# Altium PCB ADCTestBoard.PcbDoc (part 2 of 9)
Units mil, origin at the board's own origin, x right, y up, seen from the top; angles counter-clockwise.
Board outline 11022.62 x 9187 mil, 8 copper layers (TopLayer, InternalPlane1, InternalPlane2, InternalPlane3, InternalPlane4, InternalPlane5, MidLayer1, BottomLayer), stack 103.8 mil thick; 1282 components, 637 nets, 4473 pads, 1306 vias.
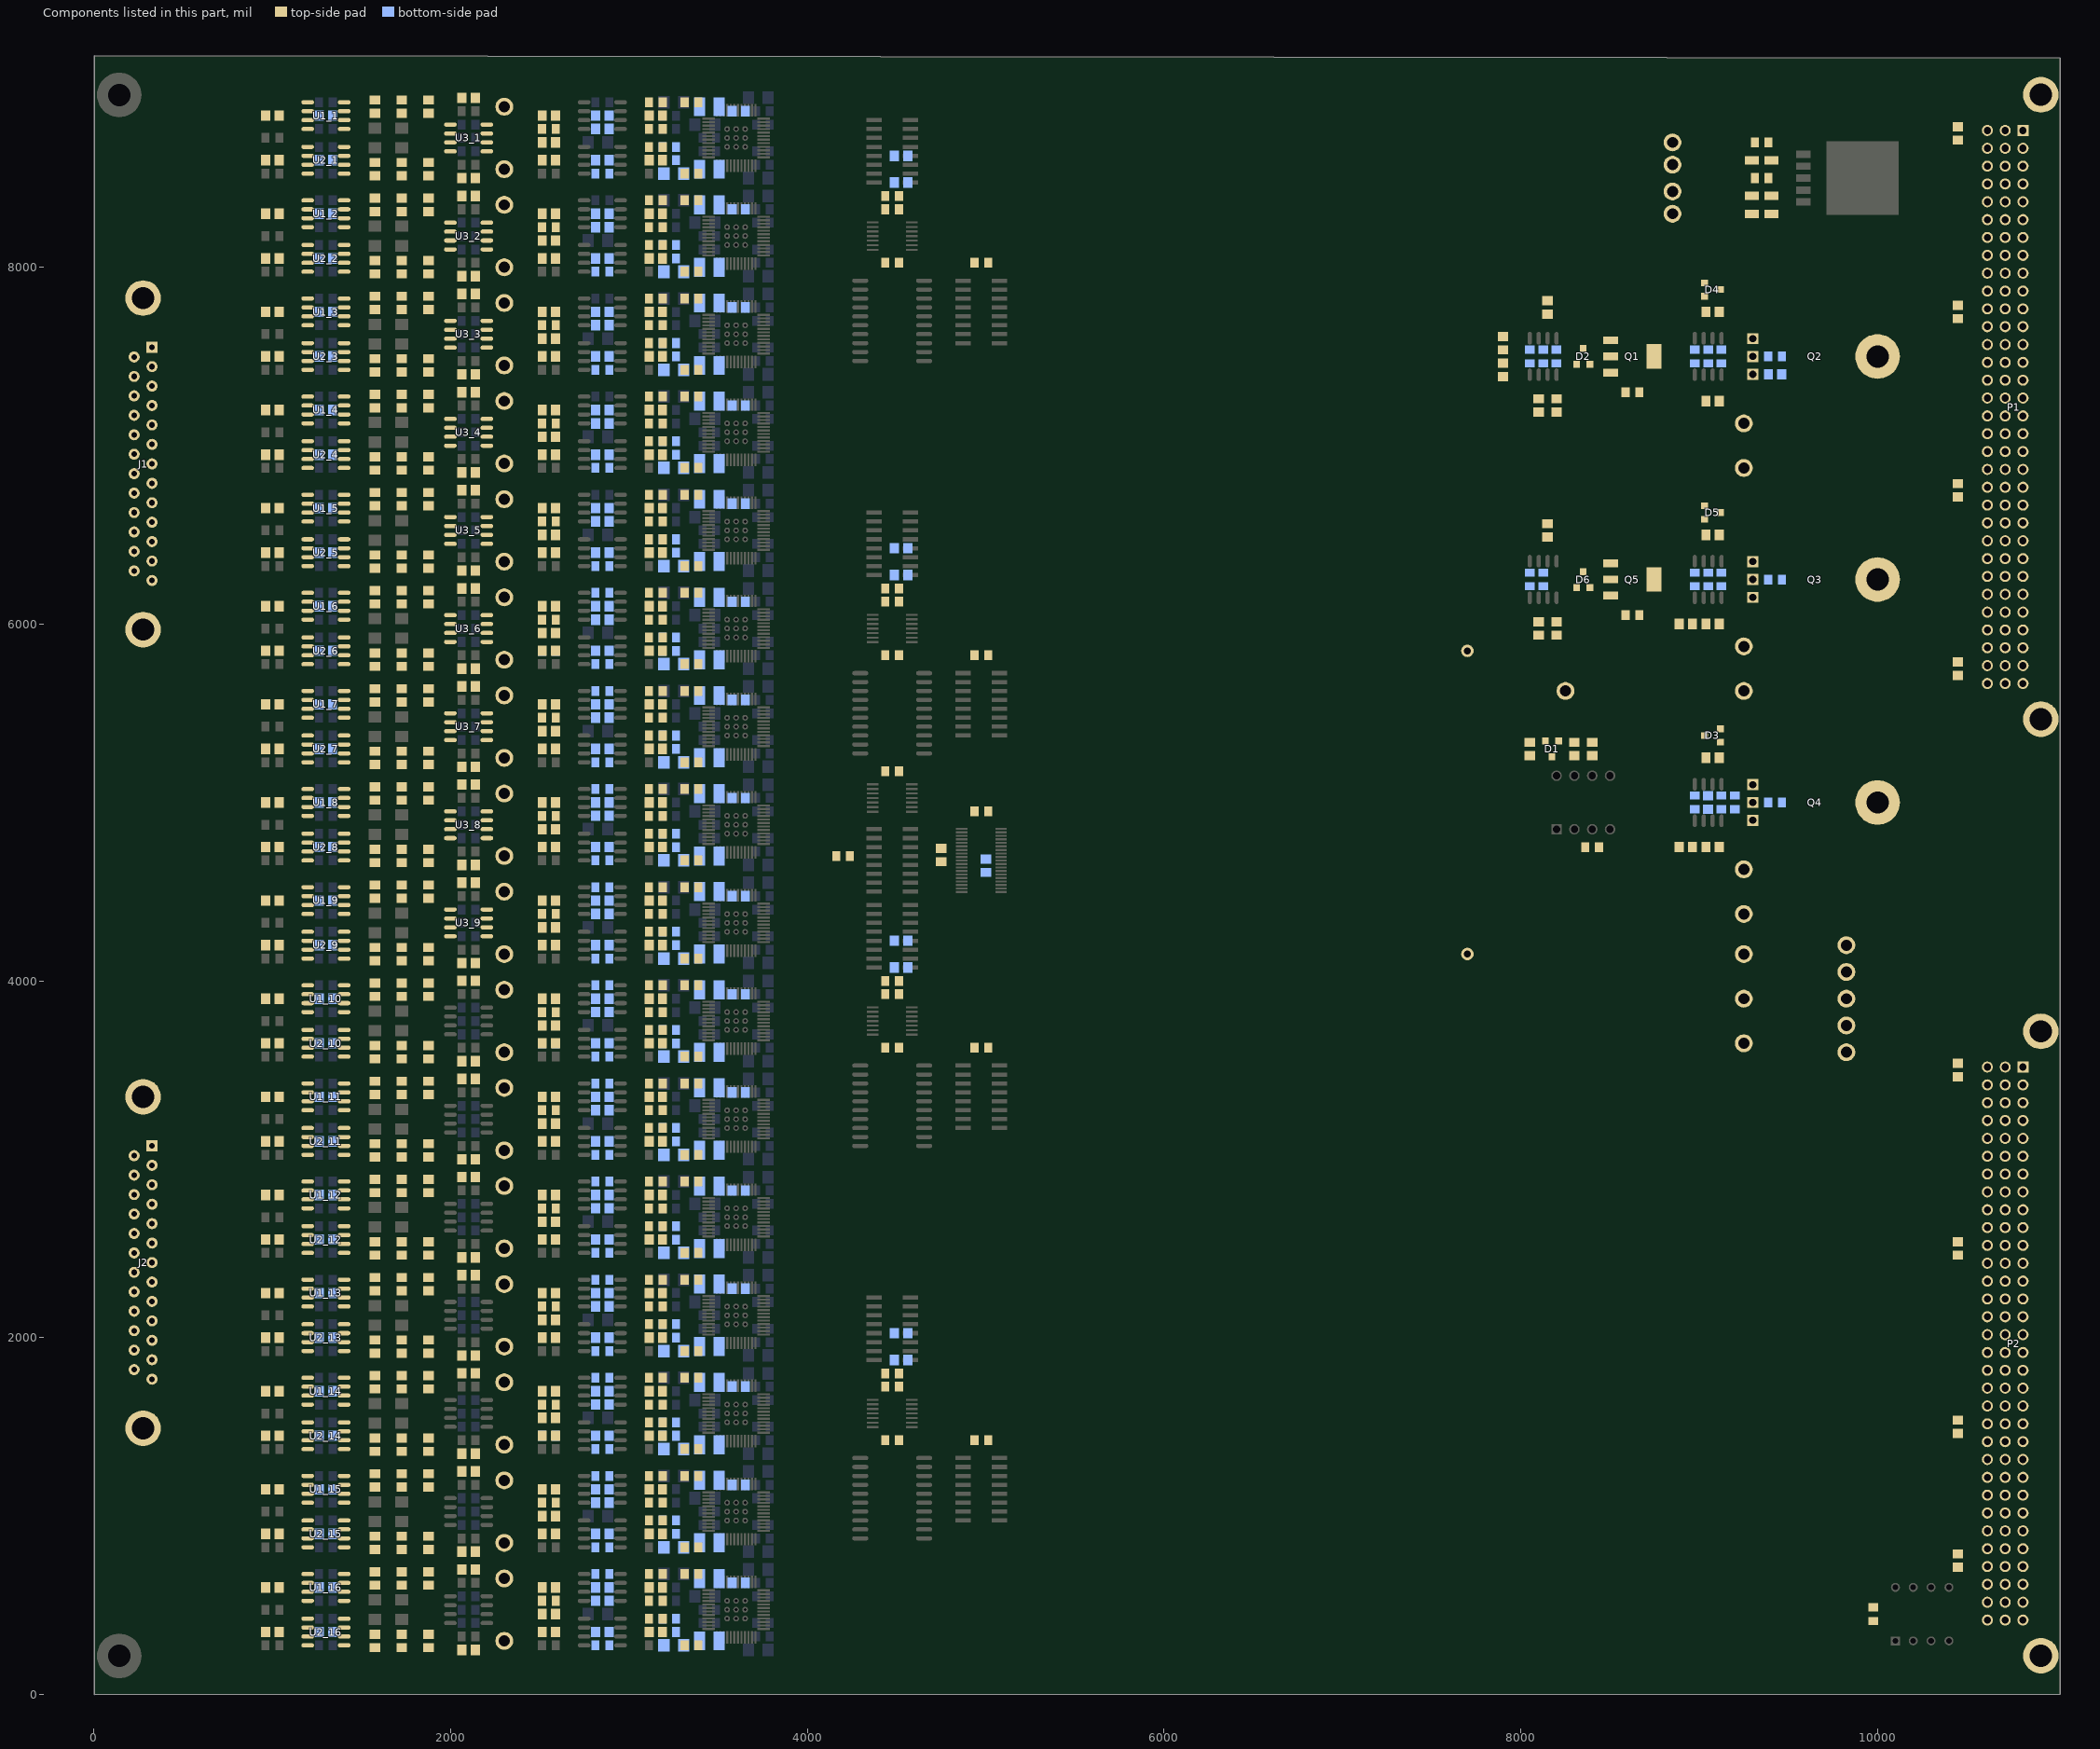
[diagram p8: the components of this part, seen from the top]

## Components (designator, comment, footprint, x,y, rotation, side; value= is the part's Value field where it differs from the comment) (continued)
C29_6 "1u" CC2013-0805 2850,6175 r180 bottom (schematic designator C29)
C29_7 "1u" CC2013-0805 2850,5625 r180 bottom (schematic designator C29)
C29_8 "1u" CC2013-0805 2850,5075 r180 bottom (schematic designator C29)
C29_9 "1u" CC2013-0805 2850,4525 r180 bottom (schematic designator C29)
C29_10 "1u" CC2013-0805 2850,3975 r180 bottom (schematic designator C29)
C29_11 "1u" CC2013-0805 2850,3425 r180 bottom (schematic designator C29)
C29_12 "1u" CC2013-0805 2850,2875 r180 bottom (schematic designator C29)
C29_13 "1u" CC2013-0805 2850,2325 r180 bottom (schematic designator C29)
C29_14 "1u" CC2013-0805 2850,1775 r180 bottom (schematic designator C29)
C29_15 "1u" CC2013-0805 2850,1225 r180 bottom (schematic designator C29)
C29_16 "1u" CC2013-0805 2850,675 r180 bottom (schematic designator C29)
C30_1 "68p" CC2013-0805 2850,8525 r180 bottom (schematic designator C30)
C30_2 "68p" CC2013-0805 2850,7975 r180 bottom (schematic designator C30)
C30_3 "68p" CC2013-0805 2850,7425 r180 bottom (schematic designator C30)
C30_4 "68p" CC2013-0805 2850,6875 r180 bottom (schematic designator C30)
C30_5 "68p" CC2013-0805 2850,6325 r180 bottom (schematic designator C30)
C30_6 "68p" CC2013-0805 2850,5775 r180 bottom (schematic designator C30)
C30_7 "68p" CC2013-0805 2850,5225 r180 bottom (schematic designator C30)
C30_8 "68p" CC2013-0805 2850,4675 r180 bottom (schematic designator C30)
C30_9 "68p" CC2013-0805 2850,4125 r180 bottom (schematic designator C30)
C30_10 "68p" CC2013-0805 2850,3575 r180 bottom (schematic designator C30)
C30_11 "68p" CC2013-0805 2850,3025 r180 bottom (schematic designator C30)
C30_12 "68p" CC2013-0805 2850,2475 r180 bottom (schematic designator C30)
C30_13 "68p" CC2013-0805 2850,1925 r180 bottom (schematic designator C30)
C30_14 "68p" CC2013-0805 2850,1375 r180 bottom (schematic designator C30)
C30_15 "68p" CC2013-0805 2850,825 r180 bottom (schematic designator C30)
C30_16 "68p" CC2013-0805 2850,275 r180 bottom (schematic designator C30)
C31_1 "47u" CC3225-1210 3450,8900 r0 bottom (schematic designator C31)
C31_2 "47u" CC3225-1210 3450,8350 r0 bottom (schematic designator C31)
C31_3 "47u" CC3225-1210 3450,7800 r0 bottom (schematic designator C31)
C31_4 "47u" CC3225-1210 3450,7250 r0 bottom (schematic designator C31)
C31_5 "47u" CC3225-1210 3450,6700 r0 bottom (schematic designator C31)
C31_6 "47u" CC3225-1210 3450,6150 r0 bottom (schematic designator C31)
C31_7 "47u" CC3225-1210 3450,5600 r0 bottom (schematic designator C31)
C31_8 "47u" CC3225-1210 3450,5050 r0 bottom (schematic designator C31)
C31_9 "47u" CC3225-1210 3450,4500 r0 bottom (schematic designator C31)
C31_10 "47u" CC3225-1210 3450,3950 r0 bottom (schematic designator C31)
C31_11 "47u" CC3225-1210 3450,3400 r0 bottom (schematic designator C31)
C31_12 "47u" CC3225-1210 3450,2850 r0 bottom (schematic designator C31)
C31_13 "47u" CC3225-1210 3450,2300 r0 bottom (schematic designator C31)
C31_14 "47u" CC3225-1210 3450,1750 r0 bottom (schematic designator C31)
C31_15 "47u" CC3225-1210 3450,1200 r0 bottom (schematic designator C31)
C31_16 "47u" CC3225-1210 3450,650 r0 bottom (schematic designator C31)
C32_1 "1u" CC2013-0805 3350,8925 r180 top (schematic designator C32)
C32_2 "1u" CC2013-0805 3350,8375 r180 top (schematic designator C32)
C32_3 "1u" CC2013-0805 3350,7825 r180 top (schematic designator C32)
C32_4 "1u" CC2013-0805 3350,7275 r180 top (schematic designator C32)
C32_5 "1u" CC2013-0805 3350,6725 r180 top (schematic designator C32)
C32_6 "1u" CC2013-0805 3350,6175 r180 top (schematic designator C32)
C32_7 "1u" CC2013-0805 3350,5625 r180 top (schematic designator C32)
C32_8 "1u" CC2013-0805 3350,5075 r180 top (schematic designator C32)
C32_9 "1u" CC2013-0805 3350,4525 r180 top (schematic designator C32)
C32_10 "1u" CC2013-0805 3350,3975 r180 top (schematic designator C32)
C32_11 "1u" CC2013-0805 3350,3425 r180 top (schematic designator C32)
C32_12 "1u" CC2013-0805 3350,2875 r180 top (schematic designator C32)
C32_13 "1u" CC2013-0805 3350,2325 r180 top (schematic designator C32)
C32_14 "1u" CC2013-0805 3350,1775 r180 top (schematic designator C32)
C32_15 "1u" CC2013-0805 3350,1225 r180 top (schematic designator C32)
C32_16 "1u" CC2013-0805 3350,675 r180 top (schematic designator C32)
C33_1 "1u" CC2013-0805 3350,8525 r0 top (schematic designator C33)
C33_2 "1u" CC2013-0805 3350,7975 r0 top (schematic designator C33)
C33_3 "1u" CC2013-0805 3350,7425 r0 top (schematic designator C33)
C33_4 "1u" CC2013-0805 3350,6875 r0 top (schematic designator C33)
C33_5 "1u" CC2013-0805 3350,6325 r0 top (schematic designator C33)
C33_6 "1u" CC2013-0805 3350,5775 r0 top (schematic designator C33)
C33_7 "1u" CC2013-0805 3350,5225 r0 top (schematic designator C33)
C33_8 "1u" CC2013-0805 3350,4675 r0 top (schematic designator C33)
C33_9 "1u" CC2013-0805 3350,4125 r0 top (schematic designator C33)
C33_10 "1u" CC2013-0805 3350,3575 r0 top (schematic designator C33)
C33_11 "1u" CC2013-0805 3350,3025 r0 top (schematic designator C33)
C33_12 "1u" CC2013-0805 3350,2475 r0 top (schematic designator C33)
C33_13 "1u" CC2013-0805 3350,1925 r0 top (schematic designator C33)
C33_14 "1u" CC2013-0805 3350,1375 r0 top (schematic designator C33)
C33_15 "1u" CC2013-0805 3350,825 r0 top (schematic designator C33)
C33_16 "1u" CC2013-0805 3350,275 r0 top (schematic designator C33)
C34_1 "120p" CC2013-0805 2550,8600 r180 bottom (schematic designator C34)
C34_2 "120p" CC2013-0805 2550,8050 r180 bottom (schematic designator C34)
C34_3 "120p" CC2013-0805 2550,7500 r180 bottom (schematic designator C34)
C34_4 "120p" CC2013-0805 2550,6950 r180 bottom (schematic designator C34)
C34_5 "120p" CC2013-0805 2550,6400 r180 bottom (schematic designator C34)
C34_6 "120p" CC2013-0805 2550,5850 r180 bottom (schematic designator C34)
C34_7 "120p" CC2013-0805 2550,5300 r180 bottom (schematic designator C34)
C34_8 "120p" CC2013-0805 2550,4750 r180 bottom (schematic designator C34)
C34_9 "120p" CC2013-0805 2550,4200 r180 bottom (schematic designator C34)
C34_10 "120p" CC2013-0805 2550,3650 r180 bottom (schematic designator C34)
C34_11 "120p" CC2013-0805 2550,3100 r180 bottom (schematic designator C34)
C34_12 "120p" CC2013-0805 2550,2550 r180 bottom (schematic designator C34)
C34_13 "120p" CC2013-0805 2550,2000 r180 bottom (schematic designator C34)
C34_14 "120p" CC2013-0805 2550,1450 r180 bottom (schematic designator C34)
C34_15 "120p" CC2013-0805 2550,900 r180 bottom (schematic designator C34)
C34_16 "120p" CC2013-0805 2550,350 r180 bottom (schematic designator C34)
C35_1 "47u" CC3225-1210 3450,8550 r0 bottom (schematic designator C35)
C35_2 "47u" CC3225-1210 3450,8000 r0 bottom (schematic designator C35)
C35_3 "47u" CC3225-1210 3450,7450 r0 bottom (schematic designator C35)
C35_4 "47u" CC3225-1210 3450,6900 r0 bottom (schematic designator C35)
C35_5 "47u" CC3225-1210 3450,6350 r0 bottom (schematic designator C35)
C35_6 "47u" CC3225-1210 3450,5800 r0 bottom (schematic designator C35)
C35_7 "47u" CC3225-1210 3450,5250 r0 bottom (schematic designator C35)
C35_8 "47u" CC3225-1210 3450,4700 r0 bottom (schematic designator C35)
C35_9 "47u" CC3225-1210 3450,4150 r0 bottom (schematic designator C35)
C35_10 "47u" CC3225-1210 3450,3600 r0 bottom (schematic designator C35)
C35_11 "47u" CC3225-1210 3450,3050 r0 bottom (schematic designator C35)
C35_12 "47u" CC3225-1210 3450,2500 r0 bottom (schematic designator C35)
C35_13 "47u" CC3225-1210 3450,1950 r0 bottom (schematic designator C35)
C35_14 "47u" CC3225-1210 3450,1400 r0 bottom (schematic designator C35)
C35_15 "47u" CC3225-1210 3450,850 r0 bottom (schematic designator C35)
C35_16 "47u" CC3225-1210 3450,300 r0 bottom (schematic designator C35)
C36_1 "NL" CC2013-0805 3150,8925 r180 top (schematic designator C36)
C36_2 "NL" CC2013-0805 3150,8375 r180 top (schematic designator C36)
C36_3 "NL" CC2013-0805 3150,7825 r180 top (schematic designator C36)
C36_4 "NL" CC2013-0805 3150,7275 r180 top (schematic designator C36)
C36_5 "NL" CC2013-0805 3150,6725 r180 top (schematic designator C36)
C36_6 "NL" CC2013-0805 3150,6175 r180 top (schematic designator C36)
C36_7 "NL" CC2013-0805 3150,5625 r180 top (schematic designator C36)
C36_8 "NL" CC2013-0805 3150,5075 r180 top (schematic designator C36)
C36_9 "NL" CC2013-0805 3150,4525 r180 top (schematic designator C36)
C36_10 "NL" CC2013-0805 3150,3975 r180 top (schematic designator C36)
C36_11 "NL" CC2013-0805 3150,3425 r180 top (schematic designator C36)
C36_12 "NL" CC2013-0805 3150,2875 r180 top (schematic designator C36)
C36_13 "NL" CC2013-0805 3150,2325 r180 top (schematic designator C36)
C36_14 "NL" CC2013-0805 3150,1775 r180 top (schematic designator C36)
C36_15 "NL" CC2013-0805 3150,1225 r180 top (schematic designator C36)
C36_16 "NL" CC2013-0805 3150,675 r180 top (schematic designator C36)
C37_1 "68p" CC2013-0805 3150,8775 r0 top (schematic designator C37)
C37_2 "68p" CC2013-0805 3150,8225 r0 top (schematic designator C37)
C37_3 "68p" CC2013-0805 3150,7675 r0 top (schematic designator C37)
C37_4 "68p" CC2013-0805 3150,7125 r0 top (schematic designator C37)
C37_5 "68p" CC2013-0805 3150,6575 r0 top (schematic designator C37)
C37_6 "68p" CC2013-0805 3150,6025 r0 top (schematic designator C37)
C37_7 "68p" CC2013-0805 3150,5475 r0 top (schematic designator C37)
C37_8 "68p" CC2013-0805 3150,4925 r0 top (schematic designator C37)
C37_9 "68p" CC2013-0805 3150,4375 r0 top (schematic designator C37)
C37_10 "68p" CC2013-0805 3150,3825 r0 top (schematic designator C37)
C37_11 "68p" CC2013-0805 3150,3275 r0 top (schematic designator C37)
C37_12 "68p" CC2013-0805 3150,2725 r0 top (schematic designator C37)
C37_13 "68p" CC2013-0805 3150,2175 r0 top (schematic designator C37)
C37_14 "68p" CC2013-0805 3150,1625 r0 top (schematic designator C37)
C37_15 "68p" CC2013-0805 3150,1075 r0 top (schematic designator C37)
C37_16 "68p" CC2013-0805 3150,525 r0 top (schematic designator C37)
C38_1 "1u" CC2013-0805 3150,8675 r0 top (schematic designator C38)
C38_2 "1u" CC2013-0805 3150,8125 r0 top (schematic designator C38)
C38_3 "1u" CC2013-0805 3150,7575 r0 top (schematic designator C38)
C38_4 "1u" CC2013-0805 3150,7025 r0 top (schematic designator C38)
C38_5 "1u" CC2013-0805 3150,6475 r0 top (schematic designator C38)
C38_6 "1u" CC2013-0805 3150,5925 r0 top (schematic designator C38)
C38_7 "1u" CC2013-0805 3150,5375 r0 top (schematic designator C38)
C38_8 "1u" CC2013-0805 3150,4825 r0 top (schematic designator C38)
C38_9 "1u" CC2013-0805 3150,4275 r0 top (schematic designator C38)
C38_10 "1u" CC2013-0805 3150,3725 r0 top (schematic designator C38)
C38_11 "1u" CC2013-0805 3150,3175 r0 top (schematic designator C38)
C38_12 "1u" CC2013-0805 3150,2625 r0 top (schematic designator C38)
C38_13 "1u" CC2013-0805 3150,2075 r0 top (schematic designator C38)
C38_14 "1u" CC2013-0805 3150,1525 r0 top (schematic designator C38)
C38_15 "1u" CC2013-0805 3150,975 r0 top (schematic designator C38)
C38_16 "1u" CC2013-0805 3150,425 r0 top (schematic designator C38)
C39_1 "1u" CC2013-0805 2550,8775 r180 top (schematic designator C39)
C39_2 "1u" CC2013-0805 2550,8225 r180 top (schematic designator C39)
C39_3 "1u" CC2013-0805 2550,7675 r180 top (schematic designator C39)
C39_4 "1u" CC2013-0805 2550,7125 r180 top (schematic designator C39)
C39_5 "1u" CC2013-0805 2550,6575 r180 top (schematic designator C39)
C39_6 "1u" CC2013-0805 2550,6025 r180 top (schematic designator C39)
C39_7 "1u" CC2013-0805 2550,5475 r180 top (schematic designator C39)
C39_8 "1u" CC2013-0805 2550,4925 r180 top (schematic designator C39)
C39_9 "1u" CC2013-0805 2550,4375 r180 top (schematic designator C39)
C39_10 "1u" CC2013-0805 2550,3825 r180 top (schematic designator C39)
C39_11 "1u" CC2013-0805 2550,3275 r180 top (schematic designator C39)
C39_12 "1u" CC2013-0805 2550,2725 r180 top (schematic designator C39)
C39_13 "1u" CC2013-0805 2550,2175 r180 top (schematic designator C39)
C39_14 "1u" CC2013-0805 2550,1625 r180 top (schematic designator C39)
C39_15 "1u" CC2013-0805 2550,1075 r180 top (schematic designator C39)
C39_16 "1u" CC2013-0805 2550,525 r180 top (schematic designator C39)
C40_1 "10u" CC3216-1206 3250,8525 r0 bottom (schematic designator C40)
C40_2 "10u" CC3216-1206 3250,7975 r0 bottom (schematic designator C40)
C40_3 "10u" CC3216-1206 3250,7425 r0 bottom (schematic designator C40)
C40_4 "10u" CC3216-1206 3250,6875 r0 bottom (schematic designator C40)
C40_5 "10u" CC3216-1206 3250,6325 r0 bottom (schematic designator C40)
C40_6 "10u" CC3216-1206 3250,5775 r0 bottom (schematic designator C40)
C40_7 "10u" CC3216-1206 3250,5225 r0 bottom (schematic designator C40)
C40_8 "10u" CC3216-1206 3250,4675 r0 bottom (schematic designator C40)
C40_9 "10u" CC3216-1206 3250,4125 r0 bottom (schematic designator C40)
C40_10 "10u" CC3216-1206 3250,3575 r0 bottom (schematic designator C40)
C40_11 "10u" CC3216-1206 3250,3025 r0 bottom (schematic designator C40)
C40_12 "10u" CC3216-1206 3250,2475 r0 bottom (schematic designator C40)
C40_13 "10u" CC3216-1206 3250,1925 r0 bottom (schematic designator C40)
C40_14 "10u" CC3216-1206 3250,1375 r0 bottom (schematic designator C40)
C40_15 "10u" CC3216-1206 3250,825 r0 bottom (schematic designator C40)
C40_16 "10u" CC3216-1206 3250,275 r0 bottom (schematic designator C40)
C41_1 "1u" CC2013-0805 3225,8600 r0 bottom (schematic designator C41)
C41_2 "1u" CC2013-0805 3225,8050 r0 bottom (schematic designator C41)
C41_3 "1u" CC2013-0805 3225,7500 r0 bottom (schematic designator C41)
C41_4 "1u" CC2013-0805 3225,6950 r0 bottom (schematic designator C41)
C41_5 "1u" CC2013-0805 3225,6400 r0 bottom (schematic designator C41)
C41_6 "1u" CC2013-0805 3225,5850 r0 bottom (schematic designator C41)
C41_7 "1u" CC2013-0805 3225,5300 r0 bottom (schematic designator C41)
C41_8 "1u" CC2013-0805 3225,4750 r0 bottom (schematic designator C41)
C41_9 "1u" CC2013-0805 3225,4200 r0 bottom (schematic designator C41)
C41_10 "1u" CC2013-0805 3225,3650 r0 bottom (schematic designator C41)
C41_11 "1u" CC2013-0805 3225,3100 r0 bottom (schematic designator C41)
C41_12 "1u" CC2013-0805 3225,2550 r0 bottom (schematic designator C41)
C41_13 "1u" CC2013-0805 3225,2000 r0 bottom (schematic designator C41)
C41_14 "1u" CC2013-0805 3225,1450 r0 bottom (schematic designator C41)
C41_15 "1u" CC2013-0805 3225,900 r0 bottom (schematic designator C41)
C41_16 "1u" CC2013-0805 3225,350 r0 bottom (schematic designator C41)
C42_1 "100n" CC2013-0805 3225,8675 r0 bottom (schematic designator C42)
C42_2 "100n" CC2013-0805 3225,8125 r0 bottom (schematic designator C42)
C42_3 "100n" CC2013-0805 3225,7575 r0 bottom (schematic designator C42)
C42_4 "100n" CC2013-0805 3225,7025 r0 bottom (schematic designator C42)
C42_5 "100n" CC2013-0805 3225,6475 r0 bottom (schematic designator C42)
C42_6 "100n" CC2013-0805 3225,5925 r0 bottom (schematic designator C42)
C42_7 "100n" CC2013-0805 3225,5375 r0 bottom (schematic designator C42)
C42_8 "100n" CC2013-0805 3225,4825 r0 bottom (schematic designator C42)
C42_9 "100n" CC2013-0805 3225,4275 r0 bottom (schematic designator C42)
C42_10 "100n" CC2013-0805 3225,3725 r0 bottom (schematic designator C42)
C42_11 "100n" CC2013-0805 3225,3175 r0 bottom (schematic designator C42)
C42_12 "100n" CC2013-0805 3225,2625 r0 bottom (schematic designator C42)
C42_13 "100n" CC2013-0805 3225,2075 r0 bottom (schematic designator C42)
C42_14 "100n" CC2013-0805 3225,1525 r0 bottom (schematic designator C42)
C42_15 "100n" CC2013-0805 3225,975 r0 bottom (schematic designator C42)
C42_16 "100n" CC2013-0805 3225,425 r0 bottom (schematic designator C42)
C43_1 "100n" CC2013-0805 4475,8400 r0 top (schematic designator C43)
C43_2 "100n" CC2013-0805 4475,6200 r0 top (schematic designator C43)
C43_3 "100n" CC2013-0805 4475,4000 r0 top (schematic designator C43)
C43_4 "100n" CC2013-0805 4475,1800 r0 top (schematic designator C43)
C44_1 "100n" CC2013-0805 4475,8025 r180 top (schematic designator C44)
C44_2 "100n" CC2013-0805 4475,5825 r180 top (schematic designator C44)
C44_3 "100n" CC2013-0805 4475,3625 r180 top (schematic designator C44)
C44_4 "100n" CC2013-0805 4475,1425 r180 top (schematic designator C44)
C45_1 "100n" CC2013-0805 4975,8025 r0 top (schematic designator C45)
C45_2 "100n" CC2013-0805 4975,5825 r0 top (schematic designator C45)
C45_3 "100n" CC2013-0805 4975,3625 r0 top (schematic designator C45)
C45_4 "100n" CC2013-0805 4975,1425 r0 top (schematic designator C45)
C46_1 "100n" CC2013-0805 4475,8325 r180 top (schematic designator C46)
C46_2 "100n" CC2013-0805 4475,6125 r180 top (schematic designator C46)
C46_3 "100n" CC2013-0805 4475,3925 r180 top (schematic designator C46)
C46_4 "100n" CC2013-0805 4475,1725 r180 top (schematic designator C46)
C47 "100n" CC2013-0805 8625,7300 r180 top
C48 "68p" CC2013-0805 8200,7500 r270 bottom
C49 "100n" CC2013-0805 8625,6050 r0 top
C50 "100n" CC2013-0805 8050,7500 r90 bottom
C51 "100p" CC2013-0805 8125,7500 r90 bottom
C52 "100n" CC2013-0805 8400,4750 r180 top
C53 "20u" AXIAL1.7 7700,5000 r270 top
C54 "100n" CC2013-0805 9425,7500 r180 bottom
C55 "100n" CC2013-0805 9425,6250 r0 bottom
C56 "68p" CC2013-0805 9125,7500 r270 bottom
C57 "68p" CC2013-0805 9125,6250 r270 bottom
C58 "47p" CC2013-0805 8975,5000 r270 bottom
C59 "100n" CC2013-0805 8975,7500 r90 bottom
C60 "100n" CC2013-0805 8975,6250 r270 bottom
C61 "100p" CC2013-0805 9050,7500 r90 bottom
C62 "47p" CC2013-0805 9050,6250 r90 bottom
C63 "68p" CC2013-0805 9200,5000 r90 bottom
C64 "100n" CC2013-0805 9125,5000 r270 bottom
C65 "100n" CC2013-0805 9425,5000 r0 bottom
C75 "10u" TC3216-1206 9350,8600 r180 top
C76 "10u" TC3216-1206 9350,8400 r180 top
C77 "10u" TC3216-1206 9350,8300 r180 top
C78 "100n" CC2013-0805 9350,8700 r0 top
C79 "100n" CC2013-0805 9350,8500 r0 top
C80 "100n" CC2013-0805 8050,6250 r90 bottom
C81 "100p" CC2013-0805 8125,6250 r90 bottom
C82 "100n" CC2013-0805 4975,4950 r0 top
C83 "100n" CC2013-0805 4475,5175 r180 top
C84 "100n" CC2013-0805 4200,4700 r180 top
C85 "100n" CC2013-0805 9975,450 r270 top
D1 "BAS16" SO-G3/C2.25 8175,5300 r180 top
D2 "BAS16" SO-G3/C2.25 8350,7500 r0 top
D3 "BAS16" SO-G3/C2.25 9075,5375 r90 top
D4 "BAS16" SO-G3/C2.25 9075,7875 r270 top
D5 "BAS16" SO-G3/C2.25 9075,6625 r270 top
D6 "BAS16" SO-G3/C2.25 8350,6250 r0 top
J1 "D Connector 25" DB25RA/M 324.92,7552.2 r90 top
J2 "D Connector 25" DB25RA/M 325,3075 r90 top locked
P1 "DIN96" DIN96RA 10815.41,8767 r0 top locked
P2 "DIN96" DIN96RA 10815.41,3517 r0 top locked
Q1 "PZT2222A" SOT223 8625,7500 r270 top
Q2 "D44H11" TO-220H+HS 10000,7500 r270 top
Q3 "D44H11" TO-220H+HS 10000,6250 r270 top
Q4 "D45H11" TO-220H+HS 10000,5000 r270 top
Q5 "PZT2222A" SOT223 8625,6250 r270 top
R1_1 "100" CR2012-0805 1300,8850 r0 bottom (schematic designator R1)
R1_2 "100" CR2012-0805 1300,8300 r0 bottom (schematic designator R1)
R1_3 "100" CR2012-0805 1300,7750 r0 bottom (schematic designator R1)
R1_4 "100" CR2012-0805 1300,7200 r0 bottom (schematic designator R1)
R1_5 "100" CR2012-0805 1300,6650 r0 bottom (schematic designator R1)
R1_6 "100" CR2012-0805 1300,6100 r0 bottom (schematic designator R1)
R1_7 "100" CR2012-0805 1300,5550 r0 bottom (schematic designator R1)
R1_8 "100" CR2012-0805 1300,5000 r0 bottom (schematic designator R1)
R1_9 "100" CR2012-0805 1300,4450 r0 bottom (schematic designator R1)
R1_10 "100" CR2012-0805 1300,3900 r0 bottom (schematic designator R1)
R1_11 "100" CR2012-0805 1300,3350 r0 bottom (schematic designator R1)
R1_12 "100" CR2012-0805 1300,2800 r0 bottom (schematic designator R1)
R1_13 "100" CR2012-0805 1300,2250 r0 bottom (schematic designator R1)
R1_14 "100" CR2012-0805 1300,1700 r0 bottom (schematic designator R1)
R1_15 "100" CR2012-0805 1300,1150 r0 bottom (schematic designator R1)
R1_16 "100" CR2012-0805 1300,600 r0 bottom (schematic designator R1)
R2_1 "1k" CR2012-0805 2100,8950 r0 top (schematic designator R2)
R2_2 "1k" CR2012-0805 2100,8400 r0 top (schematic designator R2)
R2_3 "1k" CR2012-0805 2100,7850 r0 top (schematic designator R2)
R2_4 "1k" CR2012-0805 2100,7300 r0 top (schematic designator R2)
R2_5 "1k" CR2012-0805 2100,6750 r0 top (schematic designator R2)
R2_6 "1k" CR2012-0805 2100,6200 r0 top (schematic designator R2)
R2_7 "1k" CR2012-0805 2100,5650 r0 top (schematic designator R2)
R2_8 "1k" CR2012-0805 2100,5100 r0 top (schematic designator R2)
R2_9 "1k" CR2012-0805 2100,4550 r0 top (schematic designator R2)
R2_10 "1k" CR2012-0805 2100,4000 r0 top (schematic designator R2)
R2_11 "1k" CR2012-0805 2100,3450 r0 top (schematic designator R2)
R2_12 "1k" CR2012-0805 2100,2900 r0 top (schematic designator R2)
R2_13 "1k" CR2012-0805 2100,2350 r0 top (schematic designator R2)
R2_14 "1k" CR2012-0805 2100,1800 r0 top (schematic designator R2)
R2_15 "1k" CR2012-0805 2100,1250 r0 top (schematic designator R2)
R2_16 "1k" CR2012-0805 2100,700 r0 top (schematic designator R2)
R3_1 "100K" CR2012-0805 1000,8850 r180 top (schematic designator R3)
R3_2 "100K" CR2012-0805 1000,8300 r180 top (schematic designator R3)
R3_3 "100K" CR2012-0805 1000,7750 r180 top (schematic designator R3)
R3_4 "100K" CR2012-0805 1000,7200 r180 top (schematic designator R3)
R3_5 "100K" CR2012-0805 1000,6650 r180 top (schematic designator R3)
R3_6 "100K" CR2012-0805 1000,6100 r180 top (schematic designator R3)
R3_7 "100K" CR2012-0805 1000,5550 r180 top (schematic designator R3)
R3_8 "100K" CR2012-0805 1000,5000 r180 top (schematic designator R3)
R3_9 "100K" CR2012-0805 1000,4450 r180 top (schematic designator R3)
R3_10 "100K" CR2012-0805 1000,3900 r180 top (schematic designator R3)
R3_11 "100K" CR2012-0805 1000,3350 r180 top (schematic designator R3)
R3_12 "100K" CR2012-0805 1000,2800 r180 top (schematic designator R3)
R3_13 "100K" CR2012-0805 1000,2250 r180 top (schematic designator R3)
R3_14 "100K" CR2012-0805 1000,1700 r180 top (schematic designator R3)
R3_15 "100K" CR2012-0805 1000,1150 r180 top (schematic designator R3)
R3_16 "100K" CR2012-0805 1000,600 r180 top (schematic designator R3)
R4_1 "1k" CR2012-0805 1575,8900 r270 top (schematic designator R4)
R4_2 "1k" CR2012-0805 1575,8350 r270 top (schematic designator R4)
R4_3 "1k" CR2012-0805 1575,7800 r270 top (schematic designator R4)
R4_4 "1k" CR2012-0805 1575,7250 r270 top (schematic designator R4)
R4_5 "1k" CR2012-0805 1575,6700 r270 top (schematic designator R4)
R4_6 "1k" CR2012-0805 1575,6150 r270 top (schematic designator R4)
R4_7 "1k" CR2012-0805 1575,5600 r270 top (schematic designator R4)
R4_8 "1k" CR2012-0805 1575,5050 r270 top (schematic designator R4)
R4_9 "1k" CR2012-0805 1575,4500 r270 top (schematic designator R4)
R4_10 "1k" CR2012-0805 1575,3950 r270 top (schematic designator R4)
R4_11 "1k" CR2012-0805 1575,3400 r270 top (schematic designator R4)
R4_12 "1k" CR2012-0805 1575,2850 r270 top (schematic designator R4)
R4_13 "1k" CR2012-0805 1575,2300 r270 top (schematic designator R4)
R4_14 "1k" CR2012-0805 1575,1750 r270 top (schematic designator R4)
R4_15 "1k" CR2012-0805 1575,1200 r270 top (schematic designator R4)
R4_16 "1k" CR2012-0805 1575,650 r270 top (schematic designator R4)
R5_1 "1k" CR2012-0805 1725,8900 r270 top (schematic designator R5)
R5_2 "1k" CR2012-0805 1725,8350 r270 top (schematic designator R5)
R5_3 "1k" CR2012-0805 1725,7800 r270 top (schematic designator R5)
R5_4 "1k" CR2012-0805 1725,7250 r270 top (schematic designator R5)
R5_5 "1k" CR2012-0805 1725,6700 r270 top (schematic designator R5)
R5_6 "1k" CR2012-0805 1725,6150 r270 top (schematic designator R5)
R5_7 "1k" CR2012-0805 1725,5600 r270 top (schematic designator R5)
R5_8 "1k" CR2012-0805 1725,5050 r270 top (schematic designator R5)
R5_9 "1k" CR2012-0805 1725,4500 r270 top (schematic designator R5)
R5_10 "1k" CR2012-0805 1725,3950 r270 top (schematic designator R5)
R5_11 "1k" CR2012-0805 1725,3400 r270 top (schematic designator R5)
R5_12 "1k" CR2012-0805 1725,2850 r270 top (schematic designator R5)
R5_13 "1k" CR2012-0805 1725,2300 r270 top (schematic designator R5)
R5_14 "1k" CR2012-0805 1725,1750 r270 top (schematic designator R5)
R5_15 "1k" CR2012-0805 1725,1200 r270 top (schematic designator R5)
R5_16 "1k" CR2012-0805 1725,650 r270 top (schematic designator R5)
R6_1 "100" CR2012-0805 1875,8900 r270 top (schematic designator R6)
R6_2 "100" CR2012-0805 1875,8350 r270 top (schematic designator R6)
R6_3 "100" CR2012-0805 1875,7800 r270 top (schematic designator R6)
R6_4 "100" CR2012-0805 1875,7250 r270 top (schematic designator R6)
R6_5 "100" CR2012-0805 1875,6700 r270 top (schematic designator R6)
R6_6 "100" CR2012-0805 1875,6150 r270 top (schematic designator R6)
R6_7 "100" CR2012-0805 1875,5600 r270 top (schematic designator R6)
R6_8 "100" CR2012-0805 1875,5050 r270 top (schematic designator R6)
R6_9 "100" CR2012-0805 1875,4500 r270 top (schematic designator R6)
R6_10 "100" CR2012-0805 1875,3950 r270 top (schematic designator R6)
R6_11 "100" CR2012-0805 1875,3400 r270 top (schematic designator R6)
R6_12 "100" CR2012-0805 1875,2850 r270 top (schematic designator R6)
R6_13 "100" CR2012-0805 1875,2300 r270 top (schematic designator R6)
R6_14 "100" CR2012-0805 1875,1750 r270 top (schematic designator R6)
R6_15 "100" CR2012-0805 1875,1200 r270 top (schematic designator R6)
R6_16 "100" CR2012-0805 1875,650 r270 top (schematic designator R6)
R7_1 "100" CR2012-0805 1875,8550 r90 top (schematic designator R7)
R7_2 "100" CR2012-0805 1875,8000 r90 top (schematic designator R7)
R7_3 "100" CR2012-0805 1875,7450 r90 top (schematic designator R7)
R7_4 "100" CR2012-0805 1875,6900 r90 top (schematic designator R7)
R7_5 "100" CR2012-0805 1875,6350 r90 top (schematic designator R7)
R7_6 "100" CR2012-0805 1875,5800 r90 top (schematic designator R7)
R7_7 "100" CR2012-0805 1875,5250 r90 top (schematic designator R7)
R7_8 "100" CR2012-0805 1875,4700 r90 top (schematic designator R7)
R7_9 "100" CR2012-0805 1875,4150 r90 top (schematic designator R7)
R7_10 "100" CR2012-0805 1875,3600 r90 top (schematic designator R7)
R7_11 "100" CR2012-0805 1875,3050 r90 top (schematic designator R7)
R7_12 "100" CR2012-0805 1875,2500 r90 top (schematic designator R7)
R7_13 "100" CR2012-0805 1875,1950 r90 top (schematic designator R7)
R7_14 "100" CR2012-0805 1875,1400 r90 top (schematic designator R7)
R7_15 "100" CR2012-0805 1875,850 r90 top (schematic designator R7)
R7_16 "100" CR2012-0805 1875,300 r90 top (schematic designator R7)
R8_1 "10" CR2012-0805 3615,8875 r180 bottom (schematic designator R8)
R8_2 "10" CR2012-0805 3615,8325 r180 bottom (schematic designator R8)
R8_3 "10" CR2012-0805 3615,7775 r180 bottom (schematic designator R8)
R8_4 "10" CR2012-0805 3615,7225 r180 bottom (schematic designator R8)
R8_5 "10" CR2012-0805 3615,6675 r180 bottom (schematic designator R8)
R8_6 "10" CR2012-0805 3615,6125 r180 bottom (schematic designator R8)
R8_7 "10" CR2012-0805 3615,5575 r180 bottom (schematic designator R8)
R8_8 "10" CR2012-0805 3615,5025 r180 bottom (schematic designator R8)
R8_9 "10" CR2012-0805 3615,4475 r180 bottom (schematic designator R8)
R8_10 "10" CR2012-0805 3615,3925 r180 bottom (schematic designator R8)
R8_11 "10" CR2012-0805 3615,3375 r180 bottom (schematic designator R8)
R8_12 "10" CR2012-0805 3615,2825 r180 bottom (schematic designator R8)
R8_13 "10" CR2012-0805 3615,2275 r180 bottom (schematic designator R8)
R8_14 "10" CR2012-0805 3615,1725 r180 bottom (schematic designator R8)
R8_15 "10" CR2012-0805 3615,1175 r180 bottom (schematic designator R8)
R8_16 "10" CR2012-0805 3615,625 r180 bottom (schematic designator R8)
R9_1 "1k" CR2012-0805 1575,8550 r90 top (schematic designator R9)
R9_2 "1k" CR2012-0805 1575,8000 r90 top (schematic designator R9)
R9_3 "1k" CR2012-0805 1575,7450 r90 top (schematic designator R9)
R9_4 "1k" CR2012-0805 1575,6900 r90 top (schematic designator R9)
R9_5 "1k" CR2012-0805 1575,6350 r90 top (schematic designator R9)
R9_6 "1k" CR2012-0805 1575,5800 r90 top (schematic designator R9)
R9_7 "1k" CR2012-0805 1575,5250 r90 top (schematic designator R9)
R9_8 "1k" CR2012-0805 1575,4700 r90 top (schematic designator R9)
R9_9 "1k" CR2012-0805 1575,4150 r90 top (schematic designator R9)
R9_10 "1k" CR2012-0805 1575,3600 r90 top (schematic designator R9)
R9_11 "1k" CR2012-0805 1575,3050 r90 top (schematic designator R9)
R9_12 "1k" CR2012-0805 1575,2500 r90 top (schematic designator R9)
R9_13 "1k" CR2012-0805 1575,1950 r90 top (schematic designator R9)
R9_14 "1k" CR2012-0805 1575,1400 r90 top (schematic designator R9)
R9_15 "1k" CR2012-0805 1575,850 r90 top (schematic designator R9)
R9_16 "1k" CR2012-0805 1575,300 r90 top (schematic designator R9)
R10_1 "1k" CR2012-0805 1725,8550 r90 top (schematic designator R10)
R10_2 "1k" CR2012-0805 1725,8000 r90 top (schematic designator R10)
R10_3 "1k" CR2012-0805 1725,7450 r90 top (schematic designator R10)
R10_4 "1k" CR2012-0805 1725,6900 r90 top (schematic designator R10)
R10_5 "1k" CR2012-0805 1725,6350 r90 top (schematic designator R10)
R10_6 "1k" CR2012-0805 1725,5800 r90 top (schematic designator R10)
R10_7 "1k" CR2012-0805 1725,5250 r90 top (schematic designator R10)
R10_8 "1k" CR2012-0805 1725,4700 r90 top (schematic designator R10)
R10_9 "1k" CR2012-0805 1725,4150 r90 top (schematic designator R10)
R10_10 "1k" CR2012-0805 1725,3600 r90 top (schematic designator R10)
R10_11 "1k" CR2012-0805 1725,3050 r90 top (schematic designator R10)
R10_12 "1k" CR2012-0805 1725,2500 r90 top (schematic designator R10)
R10_13 "1k" CR2012-0805 1725,1950 r90 top (schematic designator R10)
R10_14 "1k" CR2012-0805 1725,1400 r90 top (schematic designator R10)
R10_15 "1k" CR2012-0805 1725,850 r90 top (schematic designator R10)
R10_16 "1k" CR2012-0805 1725,300 r90 top (schematic designator R10)
R11_1 "100K" CR2012-0805 1000,8600 r180 top (schematic designator R11)
R11_2 "100K" CR2012-0805 1000,8050 r180 top (schematic designator R11)
R11_3 "100K" CR2012-0805 1000,7500 r180 top (schematic designator R11)
R11_4 "100K" CR2012-0805 1000,6950 r180 top (schematic designator R11)
R11_5 "100K" CR2012-0805 1000,6400 r180 top (schematic designator R11)
R11_6 "100K" CR2012-0805 1000,5850 r180 top (schematic designator R11)
R11_7 "100K" CR2012-0805 1000,5300 r180 top (schematic designator R11)
R11_8 "100K" CR2012-0805 1000,4750 r180 top (schematic designator R11)
R11_9 "100K" CR2012-0805 1000,4200 r180 top (schematic designator R11)
R11_10 "100K" CR2012-0805 1000,3650 r180 top (schematic designator R11)
R11_11 "100K" CR2012-0805 1000,3100 r180 top (schematic designator R11)
R11_12 "100K" CR2012-0805 1000,2550 r180 top (schematic designator R11)
R11_13 "100K" CR2012-0805 1000,2000 r180 top (schematic designator R11)
R11_14 "100K" CR2012-0805 1000,1450 r180 top (schematic designator R11)
R11_15 "100K" CR2012-0805 1000,900 r180 top (schematic designator R11)
R11_16 "100K" CR2012-0805 1000,350 r180 top (schematic designator R11)
R12_1 "1k" CR2012-0805 2100,8500 r0 top (schematic designator R12)
R12_2 "1k" CR2012-0805 2100,7950 r0 top (schematic designator R12)
R12_3 "1k" CR2012-0805 2100,7400 r0 top (schematic designator R12)
R12_4 "1k" CR2012-0805 2100,6850 r0 top (schematic designator R12)
R12_5 "1k" CR2012-0805 2100,6300 r0 top (schematic designator R12)
R12_6 "1k" CR2012-0805 2100,5750 r0 top (schematic designator R12)
R12_7 "1k" CR2012-0805 2100,5200 r0 top (schematic designator R12)
R12_8 "1k" CR2012-0805 2100,4650 r0 top (schematic designator R12)
R12_9 "1k" CR2012-0805 2100,4100 r0 top (schematic designator R12)
R12_10 "1k" CR2012-0805 2100,3550 r0 top (schematic designator R12)
R12_11 "1k" CR2012-0805 2100,3000 r0 top (schematic designator R12)
R12_12 "1k" CR2012-0805 2100,2450 r0 top (schematic designator R12)
R12_13 "1k" CR2012-0805 2100,1900 r0 top (schematic designator R12)
R12_14 "1k" CR2012-0805 2100,1350 r0 top (schematic designator R12)
R12_15 "1k" CR2012-0805 2100,800 r0 top (schematic designator R12)
R12_16 "1k" CR2012-0805 2100,250 r0 top (schematic designator R12)
R13_1 "100" CR2012-0805 1300,8600 r0 bottom (schematic designator R13)
R13_2 "100" CR2012-0805 1300,8050 r0 bottom (schematic designator R13)
R13_3 "100" CR2012-0805 1300,7500 r0 bottom (schematic designator R13)
R13_4 "100" CR2012-0805 1300,6950 r0 bottom (schematic designator R13)
R13_5 "100" CR2012-0805 1300,6400 r0 bottom (schematic designator R13)
R13_6 "100" CR2012-0805 1300,5850 r0 bottom (schematic designator R13)
R13_7 "100" CR2012-0805 1300,5300 r0 bottom (schematic designator R13)
R13_8 "100" CR2012-0805 1300,4750 r0 bottom (schematic designator R13)
R13_9 "100" CR2012-0805 1300,4200 r0 bottom (schematic designator R13)
R13_10 "100" CR2012-0805 1300,3650 r0 bottom (schematic designator R13)
R13_11 "100" CR2012-0805 1300,3100 r0 bottom (schematic designator R13)
R13_12 "100" CR2012-0805 1300,2550 r0 bottom (schematic designator R13)
R13_13 "100" CR2012-0805 1300,2000 r0 bottom (schematic designator R13)
R13_14 "100" CR2012-0805 1300,1450 r0 bottom (schematic designator R13)
R13_15 "100" CR2012-0805 1300,900 r0 bottom (schematic designator R13)
R13_16 "100" CR2012-0805 1300,350 r0 bottom (schematic designator R13)
R14_1 "0" CR2012-0805 3150,8600 r180 top (schematic designator R14)
R14_2 "0" CR2012-0805 3150,8050 r180 top (schematic designator R14)
R14_3 "0" CR2012-0805 3150,7500 r180 top (schematic designator R14)
R14_4 "0" CR2012-0805 3150,6950 r180 top (schematic designator R14)
R14_5 "0" CR2012-0805 3150,6400 r180 top (schematic designator R14)
R14_6 "0" CR2012-0805 3150,5850 r180 top (schematic designator R14)
R14_7 "0" CR2012-0805 3150,5300 r180 top (schematic designator R14)
R14_8 "0" CR2012-0805 3150,4750 r180 top (schematic designator R14)
R14_9 "0" CR2012-0805 3150,4200 r180 top (schematic designator R14)
R14_10 "0" CR2012-0805 3150,3650 r180 top (schematic designator R14)
R14_11 "0" CR2012-0805 3150,3100 r180 top (schematic designator R14)
R14_12 "0" CR2012-0805 3150,2550 r180 top (schematic designator R14)
R14_13 "0" CR2012-0805 3150,2000 r180 top (schematic designator R14)
R14_14 "0" CR2012-0805 3150,1450 r180 top (schematic designator R14)
R14_15 "0" CR2012-0805 3150,900 r180 top (schematic designator R14)
R14_16 "0" CR2012-0805 3150,350 r180 top (schematic designator R14)
R15_1 "1k" CR2012-0805 2850,8850 r180 bottom (schematic designator R15)
R15_2 "1k" CR2012-0805 2850,8300 r180 bottom (schematic designator R15)
R15_3 "1k" CR2012-0805 2850,7750 r180 bottom (schematic designator R15)
R15_4 "1k" CR2012-0805 2850,7200 r180 bottom (schematic designator R15)
R15_5 "1k" CR2012-0805 2850,6650 r180 bottom (schematic designator R15)
R15_6 "1k" CR2012-0805 2850,6100 r180 bottom (schematic designator R15)
R15_7 "1k" CR2012-0805 2850,5550 r180 bottom (schematic designator R15)
R15_8 "1k" CR2012-0805 2850,5000 r180 bottom (schematic designator R15)
R15_9 "1k" CR2012-0805 2850,4450 r180 bottom (schematic designator R15)
R15_10 "1k" CR2012-0805 2850,3900 r180 bottom (schematic designator R15)
R15_11 "1k" CR2012-0805 2850,3350 r180 bottom (schematic designator R15)
R15_12 "1k" CR2012-0805 2850,2800 r180 bottom (schematic designator R15)
R15_13 "1k" CR2012-0805 2850,2250 r180 bottom (schematic designator R15)
R15_14 "1k" CR2012-0805 2850,1700 r180 bottom (schematic designator R15)
R15_15 "1k" CR2012-0805 2850,1150 r180 bottom (schematic designator R15)
R15_16 "1k" CR2012-0805 2850,600 r180 bottom (schematic designator R15)
R16_1 "1k" CR2012-0805 2850,8775 r0 bottom (schematic designator R16)
R16_2 "1k" CR2012-0805 2850,8225 r0 bottom (schematic designator R16)
R16_3 "1k" CR2012-0805 2850,7675 r0 bottom (schematic designator R16)
R16_4 "1k" CR2012-0805 2850,7125 r0 bottom (schematic designator R16)
R16_5 "1k" CR2012-0805 2850,6575 r0 bottom (schematic designator R16)
R16_6 "1k" CR2012-0805 2850,6025 r0 bottom (schematic designator R16)
R16_7 "1k" CR2012-0805 2850,5475 r0 bottom (schematic designator R16)
R16_8 "1k" CR2012-0805 2850,4925 r0 bottom (schematic designator R16)
R16_9 "1k" CR2012-0805 2850,4375 r0 bottom (schematic designator R16)
R16_10 "1k" CR2012-0805 2850,3825 r0 bottom (schematic designator R16)
R16_11 "1k" CR2012-0805 2850,3275 r0 bottom (schematic designator R16)
R16_12 "1k" CR2012-0805 2850,2725 r0 bottom (schematic designator R16)
R16_13 "1k" CR2012-0805 2850,2175 r0 bottom (schematic designator R16)
R16_14 "1k" CR2012-0805 2850,1625 r0 bottom (schematic designator R16)
R16_15 "1k" CR2012-0805 2850,1075 r0 bottom (schematic designator R16)
R16_16 "1k" CR2012-0805 2850,525 r0 bottom (schematic designator R16)
R17_1 "680" CR2012-0805 2550,8700 r0 top (schematic designator R17)
R17_2 "680" CR2012-0805 2550,8150 r0 top (schematic designator R17)
R17_3 "680" CR2012-0805 2550,7600 r0 top (schematic designator R17)
R17_4 "680" CR2012-0805 2550,7050 r0 top (schematic designator R17)
R17_5 "680" CR2012-0805 2550,6500 r0 top (schematic designator R17)
R17_6 "680" CR2012-0805 2550,5950 r0 top (schematic designator R17)
R17_7 "680" CR2012-0805 2550,5400 r0 top (schematic designator R17)
R17_8 "680" CR2012-0805 2550,4850 r0 top (schematic designator R17)
R17_9 "680" CR2012-0805 2550,4300 r0 top (schematic designator R17)
R17_10 "680" CR2012-0805 2550,3750 r0 top (schematic designator R17)
R17_11 "680" CR2012-0805 2550,3200 r0 top (schematic designator R17)
R17_12 "680" CR2012-0805 2550,2650 r0 top (schematic designator R17)
R17_13 "680" CR2012-0805 2550,2100 r0 top (schematic designator R17)
R17_14 "680" CR2012-0805 2550,1550 r0 top (schematic designator R17)
R17_15 "680" CR2012-0805 2550,1000 r0 top (schematic designator R17)
R17_16 "680" CR2012-0805 2550,450 r0 top (schematic designator R17)
R18_1 "750" CR2012-0805 2550,8600 r0 top (schematic designator R18)
R18_2 "750" CR2012-0805 2550,8050 r0 top (schematic designator R18)
R18_3 "750" CR2012-0805 2550,7500 r0 top (schematic designator R18)
R18_4 "750" CR2012-0805 2550,6950 r0 top (schematic designator R18)
R18_5 "750" CR2012-0805 2550,6400 r0 top (schematic designator R18)
R18_6 "750" CR2012-0805 2550,5850 r0 top (schematic designator R18)
R18_7 "750" CR2012-0805 2550,5300 r0 top (schematic designator R18)
R18_8 "750" CR2012-0805 2550,4750 r0 top (schematic designator R18)
R18_9 "750" CR2012-0805 2550,4200 r0 top (schematic designator R18)
R18_10 "750" CR2012-0805 2550,3650 r0 top (schematic designator R18)
R18_11 "750" CR2012-0805 2550,3100 r0 top (schematic designator R18)
R18_12 "750" CR2012-0805 2550,2550 r0 top (schematic designator R18)
R18_13 "750" CR2012-0805 2550,2000 r0 top (schematic designator R18)
R18_14 "750" CR2012-0805 2550,1450 r0 top (schematic designator R18)
R18_15 "750" CR2012-0805 2550,900 r0 top (schematic designator R18)
R18_16 "750" CR2012-0805 2550,350 r0 top (schematic designator R18)
R19_1 "0" CR2012-0805 3150,8850 r180 top (schematic designator R19)
R19_2 "0" CR2012-0805 3150,8300 r180 top (schematic designator R19)
R19_3 "0" CR2012-0805 3150,7750 r180 top (schematic designator R19)
R19_4 "0" CR2012-0805 3150,7200 r180 top (schematic designator R19)
R19_5 "0" CR2012-0805 3150,6650 r180 top (schematic designator R19)
R19_6 "0" CR2012-0805 3150,6100 r180 top (schematic designator R19)
R19_7 "0" CR2012-0805 3150,5550 r180 top (schematic designator R19)
R19_8 "0" CR2012-0805 3150,5000 r180 top (schematic designator R19)
R19_9 "0" CR2012-0805 3150,4450 r180 top (schematic designator R19)
R19_10 "0" CR2012-0805 3150,3900 r180 top (schematic designator R19)
R19_11 "0" CR2012-0805 3150,3350 r180 top (schematic designator R19)
R19_12 "0" CR2012-0805 3150,2800 r180 top (schematic designator R19)
R19_13 "0" CR2012-0805 3150,2250 r180 top (schematic designator R19)
R19_14 "0" CR2012-0805 3150,1700 r180 top (schematic designator R19)
R19_15 "0" CR2012-0805 3150,1150 r180 top (schematic designator R19)
R19_16 "0" CR2012-0805 3150,600 r180 top (schematic designator R19)
R20_1 "510" CR2012-0805 2550,8850 r180 top (schematic designator R20)
R20_2 "510" CR2012-0805 2550,8300 r180 top (schematic designator R20)
R20_3 "510" CR2012-0805 2550,7750 r180 top (schematic designator R20)
R20_4 "510" CR2012-0805 2550,7200 r180 top (schematic designator R20)
R20_5 "510" CR2012-0805 2550,6650 r180 top (schematic designator R20)
R20_6 "510" CR2012-0805 2550,6100 r180 top (schematic designator R20)
R20_7 "510" CR2012-0805 2550,5550 r180 top (schematic designator R20)
R20_8 "510" CR2012-0805 2550,5000 r180 top (schematic designator R20)
R20_9 "510" CR2012-0805 2550,4450 r180 top (schematic designator R20)
R20_10 "510" CR2012-0805 2550,3900 r180 top (schematic designator R20)
R20_11 "510" CR2012-0805 2550,3350 r180 top (schematic designator R20)
R20_12 "510" CR2012-0805 2550,2800 r180 top (schematic designator R20)
R20_13 "510" CR2012-0805 2550,2250 r180 top (schematic designator R20)
R20_14 "510" CR2012-0805 2550,1700 r180 top (schematic designator R20)
R20_15 "510" CR2012-0805 2550,1150 r180 top (schematic designator R20)
R20_16 "510" CR2012-0805 2550,600 r180 top (schematic designator R20)
R21_1 "100" CR2012-0805 2850,8600 r0 bottom (schematic designator R21)
R21_2 "100" CR2012-0805 2850,8050 r0 bottom (schematic designator R21)
R21_3 "100" CR2012-0805 2850,7500 r0 bottom (schematic designator R21)
R21_4 "100" CR2012-0805 2850,6950 r0 bottom (schematic designator R21)
R21_5 "100" CR2012-0805 2850,6400 r0 bottom (schematic designator R21)
R21_6 "100" CR2012-0805 2850,5850 r0 bottom (schematic designator R21)
R21_7 "100" CR2012-0805 2850,5300 r0 bottom (schematic designator R21)
R21_8 "100" CR2012-0805 2850,4750 r0 bottom (schematic designator R21)
R21_9 "100" CR2012-0805 2850,4200 r0 bottom (schematic designator R21)
R21_10 "100" CR2012-0805 2850,3650 r0 bottom (schematic designator R21)
R21_11 "100" CR2012-0805 2850,3100 r0 bottom (schematic designator R21)
R21_12 "100" CR2012-0805 2850,2550 r0 bottom (schematic designator R21)
R21_13 "100" CR2012-0805 2850,2000 r0 bottom (schematic designator R21)
R21_14 "100" CR2012-0805 2850,1450 r0 bottom (schematic designator R21)
R21_15 "100" CR2012-0805 2850,900 r0 bottom (schematic designator R21)
R21_16 "100" CR2012-0805 2850,350 r0 bottom (schematic designator R21)
R22_1 "100" CR2012-0805 4525,8475 r180 bottom (schematic designator R22)
R22_2 "100" CR2012-0805 4525,6275 r180 bottom (schematic designator R22)
R22_3 "100" CR2012-0805 4525,4075 r180 bottom (schematic designator R22)
R22_4 "100" CR2012-0805 4525,1875 r180 bottom (schematic designator R22)
R23_1 "100" CR2012-0805 4525,8625 r180 bottom (schematic designator R23)
R23_2 "100" CR2012-0805 4525,6425 r180 bottom (schematic designator R23)
R23_3 "100" CR2012-0805 4525,4225 r180 bottom (schematic designator R23)
R23_4 "100" CR2012-0805 4525,2025 r180 bottom (schematic designator R23)
R24 "100" CR2012-0805 4750,4705 r270 top
R25 "100" CR2012-0805 5000,4645 r90 bottom
R26 "100" CR2012-0805 8150,6525 r90 top
R27 "1.0K" CR2012-0805 7900,7425 r270 top
R28 "1.0K" CR2012-0805 7900,7575 r270 top
R29 "100" CR2012-0805 8150,7775 r270 top
R30 "2.4K" CR2012-0805 8200,7225 r270 top
R31 "10k" CR2012-0805 8300,5300 r270 top
R32 "680" CR2012-0805 8400,5300 r90 top
R33 "100" CR2012-0805 8050,5300 r90 top
R34 "100" CR2012-0805 8100,7225 r90 top
R35 "3.0k" CR2012-0805 9075,4750 r0 top
R36 "1.0k" CR2012-0805 8925,4750 r180 top
R37 "100" CR2012-0805 9075,7750 r180 top
R38 "100" CR2012-0805 9075,6500 r0 top
R39 "2.4K" CR2012-0805 9425,7400 r180 bottom
R40 "100" CR2012-0805 9075,5250 r0 top
R41 "750" CR2012-0805 9050,5000 r270 bottom
R42 "1.0k" CR2012-0805 8925,6000 r0 top
R43 "100" CR2012-0805 9075,7250 r180 top
R44 "2.0k" CR2012-0805 9075,6000 r0 top
R45 "0.1" CR2012-0805 10450,8750 r90 top
R46 "0.1" CR2012-0805 10450,7750 r90 top
R47 "0.1" CR2012-0805 10450,6750 r90 top
R48 "100" CR2012-0805 8100,5975 r270 top
R49 "10k" CR2012-0805 8200,5975 r270 top
R50 "0.1" CR2012-0805 10450,5750 r90 top
R51 "0.1" CR2012-0805 10450,3500 r90 top
R52 "0.1" CR2012-0805 10450,2500 r90 top
R53 "0.1" CR2012-0805 10450,1500 r90 top
R54 "0.1" CR2012-0805 10450,750 r90 top
TP1_1 "Testpoint" TP1 2300,8900 r0 top (schematic designator TP1)
TP1_2 "Testpoint" TP1 2300,8350 r0 top (schematic designator TP1)
TP1_3 "Testpoint" TP1 2300,7800 r0 top (schematic designator TP1)
TP1_4 "Testpoint" TP1 2300,7250 r0 top (schematic designator TP1)
TP1_5 "Testpoint" TP1 2300,6700 r0 top (schematic designator TP1)
TP1_6 "Testpoint" TP1 2300,6150 r0 top (schematic designator TP1)
TP1_7 "Testpoint" TP1 2300,5600 r0 top (schematic designator TP1)
TP1_8 "Testpoint" TP1 2300,5050 r0 top (schematic designator TP1)
TP1_9 "Testpoint" TP1 2300,4500 r0 top (schematic designator TP1)
TP1_10 "Testpoint" TP1 2300,3950 r0 top (schematic designator TP1)
TP1_11 "Testpoint" TP1 2300,3400 r0 top (schematic designator TP1)
TP1_12 "Testpoint" TP1 2300,2850 r0 top (schematic designator TP1)
TP1_13 "Testpoint" TP1 2300,2300 r0 top (schematic designator TP1)
TP1_14 "Testpoint" TP1 2300,1750 r0 top (schematic designator TP1)
TP1_15 "Testpoint" TP1 2300,1200 r0 top (schematic designator TP1)
TP1_16 "Testpoint" TP1 2300,650 r0 top (schematic designator TP1)
TP2_1 "Testpoint" TP1 2300,8550 r0 top (schematic designator TP2)
TP2_2 "Testpoint" TP1 2300,8000 r0 top (schematic designator TP2)
TP2_3 "Testpoint" TP1 2300,7450 r0 top (schematic designator TP2)
TP2_4 "Testpoint" TP1 2300,6900 r0 top (schematic designator TP2)
TP2_5 "Testpoint" TP1 2300,6350 r0 top (schematic designator TP2)
TP2_6 "Testpoint" TP1 2300,5800 r0 top (schematic designator TP2)
TP2_7 "Testpoint" TP1 2300,5250 r0 top (schematic designator TP2)
TP2_8 "Testpoint" TP1 2300,4700 r0 top (schematic designator TP2)
TP2_9 "Testpoint" TP1 2300,4150 r0 top (schematic designator TP2)
TP2_10 "Testpoint" TP1 2300,3600 r0 top (schematic designator TP2)
TP2_11 "Testpoint" TP1 2300,3050 r0 top (schematic designator TP2)
TP2_12 "Testpoint" TP1 2300,2500 r0 top (schematic designator TP2)
TP2_13 "Testpoint" TP1 2300,1950 r0 top (schematic designator TP2)
TP2_14 "Testpoint" TP1 2300,1400 r0 top (schematic designator TP2)
TP2_15 "Testpoint" TP1 2300,850 r0 top (schematic designator TP2)
TP2_16 "Testpoint" TP1 2300,300 r0 top (schematic designator TP2)
TP3 "Testpoint" TP1 8250,5625 r180 top
TP4 "-AV3" TP1 9825,4050 r0 top
TP5 "-AV2" TP1 9825,3750 r90 top
TP6 "DV1" TP1 8850,8700 r0 top
TP7 "+AV1" TP1 9825,3600 r0 top
TP8 "+AV2" TP1 9825,3900 r90 top
TP9 "+AV3" TP1 9825,4200 r0 top
TP10 "-15V" TP1 9250,4625 r90 top
TP11 "+5V" TP1 9250,7125 r90 top
TP12 "+15V" TP1 9250,5875 r90 top
TP13 "GND" TP1 9250,6875 r180 top
TP14 "GND" TP1 9250,5625 r270 top
TP15 "GND" TP1 9250,4375 r270 top
TP16 "GND" TP1 9250,4150 r270 top
TP17 "GND" TP1 9250,3650 r270 top
TP18 "GND" TP1 9250,3900 r180 top
TP19 "+3.3V" TP1 8850,8425 r90 top
TP20 "DGND" TP1 8850,8575 r90 top
TP21 "DGND" TP1 8850,8300 r180 top
U1_1 "AD829JR" R-8D_N 1300,8850 r0 top (schematic designator U1)
U1_2 "AD829JR" R-8D_N 1300,8300 r0 top (schematic designator U1)
U1_3 "AD829JR" R-8D_N 1300,7750 r0 top (schematic designator U1)
U1_4 "AD829JR" R-8D_N 1300,7200 r0 top (schematic designator U1)
U1_5 "AD829JR" R-8D_N 1300,6650 r0 top (schematic designator U1)
U1_6 "AD829JR" R-8D_N 1300,6100 r0 top (schematic designator U1)
U1_7 "AD829JR" R-8D_N 1300,5550 r0 top (schematic designator U1)
U1_8 "AD829JR" R-8D_N 1300,5000 r0 top (schematic designator U1)
U1_9 "AD829JR" R-8D_N 1300,4450 r0 top (schematic designator U1)
U1_10 "AD829JR" R-8D_N 1300,3900 r0 top (schematic designator U1)
U1_11 "AD829JR" R-8D_N 1300,3350 r0 top (schematic designator U1)
U1_12 "AD829JR" R-8D_N 1300,2800 r0 top (schematic designator U1)
U1_13 "AD829JR" R-8D_N 1300,2250 r0 top (schematic designator U1)
U1_14 "AD829JR" R-8D_N 1300,1700 r0 top (schematic designator U1)
U1_15 "AD829JR" R-8D_N 1300,1150 r0 top (schematic designator U1)
U1_16 "AD829JR" R-8D_N 1300,600 r0 top (schematic designator U1)
U2_1 "AD829JR" R-8D_N 1300,8600 r0 top (schematic designator U2)
U2_2 "AD829JR" R-8D_N 1300,8050 r0 top (schematic designator U2)
U2_3 "AD829JR" R-8D_N 1300,7500 r0 top (schematic designator U2)
U2_4 "AD829JR" R-8D_N 1300,6950 r0 top (schematic designator U2)
U2_5 "AD829JR" R-8D_N 1300,6400 r0 top (schematic designator U2)
U2_6 "AD829JR" R-8D_N 1300,5850 r0 top (schematic designator U2)
U2_7 "AD829JR" R-8D_N 1300,5300 r0 top (schematic designator U2)
U2_8 "AD829JR" R-8D_N 1300,4750 r0 top (schematic designator U2)
U2_9 "AD829JR" R-8D_N 1300,4200 r0 top (schematic designator U2)
U2_10 "AD829JR" R-8D_N 1300,3650 r0 top (schematic designator U2)
U2_11 "AD829JR" R-8D_N 1300,3100 r0 top (schematic designator U2)
U2_12 "AD829JR" R-8D_N 1300,2550 r0 top (schematic designator U2)
U2_13 "AD829JR" R-8D_N 1300,2000 r0 top (schematic designator U2)
U2_14 "AD829JR" R-8D_N 1300,1450 r0 top (schematic designator U2)
U2_15 "AD829JR" R-8D_N 1300,900 r0 top (schematic designator U2)
U2_16 "AD829JR" R-8D_N 1300,350 r0 top (schematic designator U2)
U3_1 "AD829JR" R-8D_N 2100,8725 r0 top (schematic designator U3)
U3_2 "AD829JR" R-8D_N 2100,8175 r0 top (schematic designator U3)
U3_3 "AD829JR" R-8D_N 2100,7625 r0 top (schematic designator U3)
U3_4 "AD829JR" R-8D_N 2100,7075 r0 top (schematic designator U3)
U3_5 "AD829JR" R-8D_N 2100,6525 r0 top (schematic designator U3)
U3_6 "AD829JR" R-8D_N 2100,5975 r0 top (schematic designator U3)
U3_7 "AD829JR" R-8D_N 2100,5425 r0 top (schematic designator U3)
U3_8 "AD829JR" R-8D_N 2100,4875 r0 top (schematic designator U3)
U3_9 "AD829JR" R-8D_N 2100,4325 r0 top (schematic designator U3)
